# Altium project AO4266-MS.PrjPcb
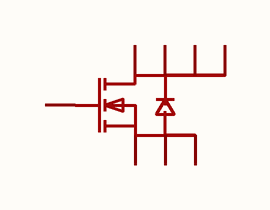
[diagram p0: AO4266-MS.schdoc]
1 sheet, 1 parts. Net scope: global (net labels, ports and power ports of the same name join across sheets).

## Sheet AO4266-MS.schdoc
size 127 x 101 mm

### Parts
Q?  ao4266-ms  [SOP-8_L4.9-W3.9-P1.27-LS6.0-BL]  (value not drawn)

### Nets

Not connected (* = marked no-connect by the designer): Q? 1(S) 2(S) 3(S) 4(G) 5(D) 6(D) 7(D) 8(D)

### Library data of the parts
Q? = ao4266-ms: 数量:1个N沟道;漏源电压(Vdss):60V;连续漏极电流(Id):10A;导通电阻(RDS(on)):10mΩ@10V;耗散功率(Pd):3W;阈值电压(Vgs(th)):1.3V;; Manufacturer: MSKSEMI(美森科); AddInBom: yes; ModelId: 75c24a7891ee4dd6bdac16a7163ff87e; ModelName: SOP-8_L4.9-W3.9-P1.27-LS6.0-BL-1; ModelTransform: 192.913,236.22,0,0,0,0,-0.393,2.749,0; Number: 1个N沟道; Drain to Source Voltage: 60V; Current - Continuous Drain(Id): 10A; Pd - Power Dissipation: 3W; Gate Threshold Voltage (Vgs(th)): 1.3V; Gate Charge(Qg): 93nC@10V; Input Capacitance(Ciss): 4.1nF; Reverse Transfer Capacitance (Crss@Vds): 229pF; Type: N沟道; Output Capacitance(Coss): 298pF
